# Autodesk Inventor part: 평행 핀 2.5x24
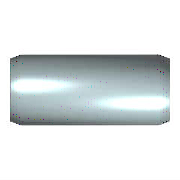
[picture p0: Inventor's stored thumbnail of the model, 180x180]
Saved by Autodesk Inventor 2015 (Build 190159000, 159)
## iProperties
IsCustomPart: 1
Created: 2012-02
Part Number: 평행 핀 2.5x24
Material: 강철, 연강
Description: 평행 핀
Document SubType Name: Modeling
Standard: KS B 1320
Designer: mduedu
Standards Organization: KS
Language: ko-KR
Size Designation: B 2.5 x  24
Categories: <MemberInstance><Categories><Category DisplayName="조임쇠" InternalName="e4da775c-781d-43d5-af7c-5136215cf5a6" Mnemonic="FSTN"><Category DisplayName="핀" InternalNa
Density: 1 g/cm^3
Appearance: 노란색
Author: mduedu
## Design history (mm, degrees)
sketch "스케치"
  geometry: C1 r 1.25 at (0, 0); 1 further point
  constraints: 1 centre point, 1 coincident
  dimensions: "d1" = 2.5 diameter of C1 (= NND)
extrude "본체" new body sketch "스케치" distance "d2" = 24 (= NLG); taper "d3" = 0 deg
chamfer "스케치2" distance "d8" = 0.4 (= PHH); stored, may be unused: angle "d9" = 15 deg (= FAWI), second distance "d12" = 0.4 (= PHH)
node "작업 평면1"
body "Solid1"
chamfer "모따기1" distance "d4" = 0.4 (= PHH); stored, may be unused: angle "d5" = 15 deg (= FAWI), second distance "d11" = 0.4 (= PHH)
other parameters: "NND" = 2.5 [user parameter; used in 1 equation term], "NLG" = 24 [user parameter; used in 1 equation term], "PHH" = 0.4 [user parameter; used in 4 equation terms], "FAWI" = 15 deg [user parameter; used in 2 equation terms], "d13" = 0, "d15" = 0, "d16" = 0, "KAH" = 0.3 [user parameter]
